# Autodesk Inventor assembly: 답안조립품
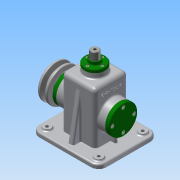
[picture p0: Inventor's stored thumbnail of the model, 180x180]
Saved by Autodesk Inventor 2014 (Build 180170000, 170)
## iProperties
Created: 2015-12
Part Number: 답안조립품
Document SubType Name: Assembly
Designer: Administrator
Author: Administrator
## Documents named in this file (19)
- D:\451225V1013\답안조립품.iam
- D:\451225V1013\본체.ipt
- D:\451225V1013\편심축.ipt
- D:\451225V1013\볼트 M6 x 12.ipt
- D:\451225V1013\와셔.ipt
- D:\451225V1013\키 5 x 5 x 14.ipt
- D:\451225V1013\V-벨트풀리.ipt
- D:\451225V1013\멈춤링 15 x 1.ipt
- D:\451225V1013\베어링 15 x 35 x 11.ipt
- D:\451225V1013\앞커버.ipt
- D:\451225V1013\오일실 15 25 7.ipt
- D:\451225V1013\볼트 M4 x 10.ipt
- D:\451225V1013\뒤커버.ipt
- D:\451225V1013\멈춤링 6 x 5.ipt
- D:\451225V1013\고정핀.ipt
- D:\451225V1013\링크.ipt
- D:\451225V1013\슬라이드바.ipt
- D:\451225V1013\볼트 M3 x 8.ipt
- D:\451225V1013\상부부시.ipt
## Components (15 placed, 5 different names)
1. ISO 4018 M6 x 12:1
2. V-벨트풀리:1
3. 고정핀:1
4. ISO 4762 M4 x 10:1
5. ISO 4762 M4 x 10:2
6. ISO 4762 M4 x 10:3
7. ISO 4762 M4 x 10:4
8. ISO 4762 M4 x 10:5
9. ISO 4762 M4 x 10:6
10. ISO 4762 M4 x 10:7
11. ISO 4762 M4 x 10:8
12. ISO 4762 M3 x 8:1
13. ISO 4762 M3 x 8:2
14. ISO 4762 M3 x 8:3
15. ISO 4762 M3 x 8:4
